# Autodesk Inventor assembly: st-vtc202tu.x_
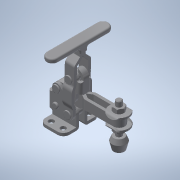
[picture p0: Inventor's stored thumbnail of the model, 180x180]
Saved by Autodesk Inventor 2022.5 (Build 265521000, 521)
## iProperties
Created: 2021-08
Part Number: st-vtc202tu.x_
Material: 一般
Document SubType Name: Assembly
Designer: ImaoCorp
Sending System: SOLIDWORKS 2019-2019304
MC: AMD64
MC_MODEL: Intel64 Family 6 Model 60 Stepping 3, GenuineIntel
OS: Windows_NT
FRU: Parasolid Version 31.0, build 290,  9- 1-2019
FORMAT: text
GUISE: transmit
KEY: st-vtc202tu
FILE: st-vtc202tu.x_t
DATE: Wed Aug  4 14:41:16 2021
Author: ImaoCorp
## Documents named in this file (8)
- X:\14_SW2022-Inv2022\00_全2023-1023新製品(TCC)まで\s\st-vtc202tu\ST-VTC202TU.iam
- X:\14_SW2022-Inv2022\00_全2023-1023新製品(TCC)まで\s\st-vtc202tu\st-vtc202tu_01.ipt
- X:\14_SW2022-Inv2022\00_全2023-1023新製品(TCC)まで\s\st-vtc202tu\st-vtc202tu_02.ipt
- X:\14_SW2022-Inv2022\00_全2023-1023新製品(TCC)まで\s\st-vtc202tu\st-vtc202tu_03.ipt
- X:\14_SW2022-Inv2022\00_全2023-1023新製品(TCC)まで\s\st-vtc202tu\st-vtc202tu_04.ipt
- X:\14_SW2022-Inv2022\00_全2023-1023新製品(TCC)まで\s\st-vtc202tu\st-vtc202tu_05.ipt
- X:\14_SW2022-Inv2022\00_全2023-1023新製品(TCC)まで\s\st-vtc202tu\st-vtc202tu_06.ipt
- X:\14_SW2022-Inv2022\00_全2023-1023新製品(TCC)まで\s\st-vtc202tu\st-vtc202tu_07.ipt
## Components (7 placed, 7 different names)
1. st-vtc202tu_01
2. st-vtc202tu_02
3. st-vtc202tu_03
4. st-vtc202tu_04
5. st-vtc202tu_05
6. st-vtc202tu_06
7. st-vtc202tu_07
